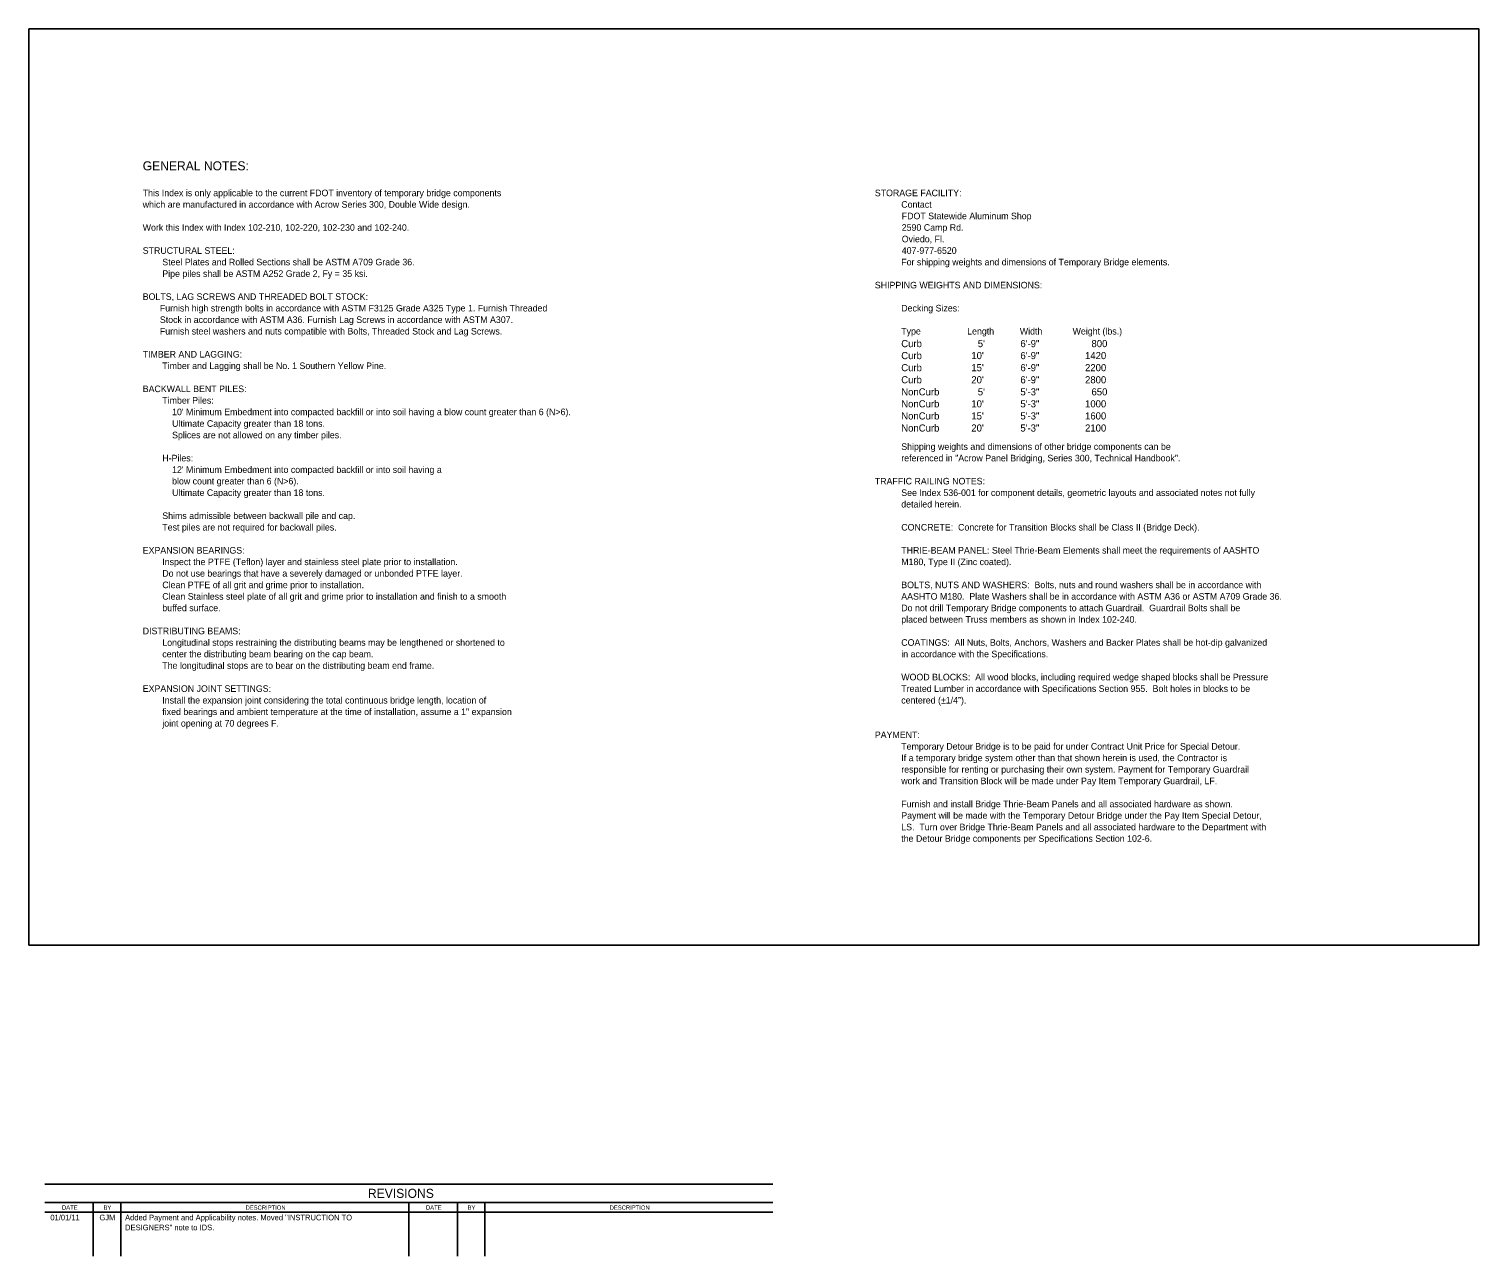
# Model space of a CAD drawing. Extents: x 0 to 2.25, y -0.21 to 0.88.
# Drawn here: x 0.001 to 1.283, y -0.211 to 0.875 of the extents above; entities that cross this region are included whole.
import ezdxf

# ---------------------------------------------------------------- set-up
doc = ezdxf.new("R2010")
doc.units = 0
for name, color, linetype in [('ActivePts-ConstElements', 7, 'Continuous'), ('Border', 7, 'Continuous'), ('TextStructures', 7, 'Continuous')]:
    doc.layers.add(name, color=color, linetype=linetype)

msp = doc.modelspace()

# ---------------------------------------------------------------- linework, layer by layer
at = {"layer": 'ActivePts-ConstElements'}
msp.add_lwpolyline([(0.0005, 0.0642), (1.2833, 0.0642), (1.2833, 0.875), (0.0005, 0.875)], close=True, dxfattribs=at)
at = {"layer": 'Border'}
for p, q in [((0.6585, -0.1475), (0.0144, -0.1475)), ((0.6585, -0.1636), (0.0144, -0.1636)), ((0.0574, -0.1636), (0.0574, -0.211)), ((0.0816, -0.1636), (0.0816, -0.211)), ((0.3365, -0.1636), (0.3365, -0.211)), ((0.3795, -0.1636), (0.3795, -0.211)), ((0.4037, -0.1636), (0.4037, -0.211)), ((0.0144, -0.1722), (0.6585, -0.1722))]:
    msp.add_line(p, q, dxfattribs=at)

# ---------------------------------------------------------------- texts
at = {"layer": 'TextStructures'}
for s, height, p in [('GENERAL NOTES:', 0.008, (0.1011, 0.7499)), ('This Index is only applicable to the current FDOT inventory of temporary bridge components', 0.005831, (0.1011, 0.727)), ('STORAGE FACILITY:', 0.005831, (0.7488, 0.727)), ('which are manufactured in accordance with Acrow Series 300, Double Wide design.', 0.005831, (0.1011, 0.7168)), ('Contact ', 0.00583, (0.7722, 0.7168)), ('           FDOT Statewide Aluminum Shop', 0.005831, (0.7488, 0.7066)), ('Work this Index with Index 102-210, 102-220, 102-230 and 102-240.', 0.005831, (0.1011, 0.6964)), ('           2590 Camp Rd.', 0.005831, (0.7488, 0.6964)), ('STRUCTURAL STEEL:', 0.005831, (0.1011, 0.676)), ('           407-977-6520', 0.005831, (0.7488, 0.676)), ('           Oviedo, Fl.', 0.005831, (0.7488, 0.6862)), ('        Steel Plates and Rolled Sections shall be ASTM A709 Grade 36. ', 0.005831, (0.1011, 0.6658)), ('For shipping weights and dimensions of Temporary Bridge elements.', 0.005831, (0.7722, 0.6658)), ('        Pipe piles shall be ASTM A252 Grade 2, Fy = 35 ksi.', 0.005831, (0.1011, 0.6556)), ('SHIPPING WEIGHTS AND DIMENSIONS:', 0.005831, (0.7488, 0.6454)), ('BOLTS, LAG SCREWS AND THREADED BOLT STOCK:', 0.005831, (0.1011, 0.6352)), ('       Furnish high strength bolts in accordance with ASTM F3125 Grade A325 Type 1. Furnish Threaded ', 0.005831, (0.1011, 0.625)), ('Decking Sizes:', 0.005831, (0.7722, 0.625)), ('       Stock in accordance with ASTM A36. Furnish Lag Screws in accordance with ASTM A307. ', 0.005831, (0.1011, 0.6148)), ('       Furnish steel washers and nuts compatible with Bolts, Threaded Stock and Lag Screws.', 0.005831, (0.1011, 0.6046)), ('Type', 0.00583, (0.7722, 0.6046)), ('Length', 0.00583, (0.8305, 0.6046)), ('Width', 0.00583, (0.8771, 0.6046)), ('Weight (lbs.)', 0.005831, (0.9238, 0.6046)), ('Curb', 0.0063, (0.7722, 0.5934)), ("5'", 0.0063, (0.8399, 0.5934)), ('6\'-9"', 0.0063, (0.8776, 0.5934)), ('800', 0.0063, (0.9405, 0.5934)), ('TIMBER AND LAGGING:', 0.005831, (0.1011, 0.5842)), ('        Timber and Lagging shall be No. 1 Southern Yellow Pine.', 0.005831, (0.1011, 0.574)), ('Curb', 0.0063, (0.7722, 0.5828)), ('Curb', 0.0063, (0.7722, 0.5721)), ("10'", 0.0063, (0.8342, 0.5828)), ("15'", 0.0063, (0.8342, 0.5721)), ('6\'-9"', 0.0063, (0.8776, 0.5828)), ('6\'-9"', 0.0063, (0.8776, 0.5721)), ('2200', 0.0063, (0.9348, 0.5721)), ('1420', 0.0063, (0.9348, 0.5828)), ('Curb', 0.0063, (0.7722, 0.5614)), ("20'", 0.0063, (0.8342, 0.5614)), ('6\'-9"', 0.0063, (0.8776, 0.5614)), ('2800', 0.0063, (0.9348, 0.5614)), ('BACKWALL BENT PILES:', 0.005831, (0.1011, 0.5536)), ('NonCurb', 0.0063, (0.7722, 0.5507)), ("5'", 0.0063, (0.8399, 0.5507)), ('5\'-3"', 0.0063, (0.8776, 0.5507)), ('650', 0.0063, (0.9405, 0.5507)), ('        Timber Piles: ', 0.005831, (0.1011, 0.5434)), ("            10' Minimum Embedment into compacted backfill or into soil having a blow count greater than 6 (N>6).", 0.005831, (0.1011, 0.5332)), ('NonCurb', 0.0063, (0.7722, 0.5401)), ("10'", 0.0063, (0.8342, 0.5401)), ('5\'-3"', 0.0063, (0.8776, 0.5401)), ('1000', 0.0063, (0.9348, 0.5401)), ('            Ultimate Capacity greater than 18 tons.', 0.005831, (0.1011, 0.5229)), ('NonCurb', 0.0063, (0.7722, 0.5294)), ("15'", 0.0063, (0.8342, 0.5294)), ('5\'-3"', 0.0063, (0.8776, 0.5294)), ('1600', 0.0063, (0.9348, 0.5294)), ('            Splices are not allowed on any timber piles.', 0.005831, (0.1011, 0.5127)), ('NonCurb', 0.0063, (0.7722, 0.5187)), ("20'", 0.0063, (0.8342, 0.5187)), ('5\'-3"', 0.0063, (0.8776, 0.5187)), ('2100', 0.0063, (0.9348, 0.5187)), ('Shipping weights and dimensions of other bridge components can be ', 0.005831, (0.7722, 0.5025)), ('        H-Piles: ', 0.005831, (0.1011, 0.4923)), ("            12' Minimum Embedment into compacted backfill or into soil having a ", 0.005831, (0.1011, 0.4821)), ('referenced in "Acrow Panel Bridging, Series 300, Technical Handbook".     ', 0.005831, (0.7722, 0.4923)), ('            blow count greater than 6 (N>6).', 0.005831, (0.1011, 0.4719)), ('TRAFFIC RAILING NOTES:', 0.005831, (0.7488, 0.4719)), ('            Ultimate Capacity greater than 18 tons.', 0.005831, (0.1011, 0.4617)), ('See Index 536-001 for component details, geometric layouts and associated notes not fully ', 0.005831, (0.7722, 0.4617)), ('detailed herein.', 0.005831, (0.7722, 0.4515)), ('        Test piles are not required for backwall piles.', 0.005831, (0.1011, 0.4311)), ('        Shims admissible between backwall pile and cap.', 0.005831, (0.1011, 0.4413)), ('CONCRETE:  Concrete for Transition Blocks shall be Class II (Bridge Deck).', 0.005831, (0.7722, 0.4311)), ('EXPANSION BEARINGS:', 0.005831, (0.1011, 0.4107)), ('THRIE-BEAM PANEL: Steel Thrie-Beam Elements shall meet the requirements of AASHTO ', 0.005831, (0.7722, 0.4107)), ('        Inspect the PTFE (Teflon) layer and stainless steel plate prior to installation.', 0.005831, (0.1011, 0.4005)), ('M180, Type II (Zinc coated).', 0.005831, (0.7722, 0.4005)), ('        Clean PTFE of all grit and grime prior to installation.', 0.005831, (0.1011, 0.3801)), ('        Do not use bearings that have a severely damaged or unbonded PTFE layer.', 0.005831, (0.1011, 0.3903)), ('BOLTS, NUTS AND WASHERS:  Bolts, nuts and round washers shall be in accordance with ', 0.005831, (0.7722, 0.3801)), ('        Clean Stainless steel plate of all grit and grime prior to installation and finish to a smooth ', 0.005831, (0.1011, 0.3699)), ('AASHTO M180.  Plate Washers shall be in accordance with ASTM A36 or ASTM A709 Grade 36.  ', 0.005831, (0.7722, 0.3699)), ('        buffed surface.', 0.005831, (0.1011, 0.3597)), ('Do not drill Temporary Bridge components to attach Guardrail.  Guardrail Bolts shall be ', 0.005831, (0.7722, 0.3597)), ('placed between Truss members as shown in Index 102-240.', 0.005831, (0.7722, 0.3495)), ('DISTRIBUTING BEAMS:', 0.005831, (0.1011, 0.3393)), ('        Longitudinal stops restraining the distributing beams may be lengthened or shortened to ', 0.005831, (0.1011, 0.3291)), ('COATINGS:  All Nuts, Bolts, Anchors, Washers and Backer Plates shall be hot-dip galvanized ', 0.005831, (0.7722, 0.3291)), ('        center the distributing beam bearing on the cap beam.', 0.005831, (0.1011, 0.3189)), ('in accordance with the Specifications.', 0.005831, (0.7722, 0.3189)), ('        The longitudinal stops are to bear on the distributing beam end frame.', 0.005831, (0.1011, 0.3087)), ('WOOD BLOCKS:  All wood blocks, including required wedge shaped blocks shall be Pressure ', 0.005831, (0.7722, 0.2985)), ('EXPANSION JOINT SETTINGS:', 0.005831, (0.1011, 0.2883)), ('        Install the expansion joint considering the total continuous bridge length, location of ', 0.005831, (0.1011, 0.278)), ('Treated Lumber in accordance with Specifications Section 955.  Bolt holes in blocks to be ', 0.005831, (0.7722, 0.2883)), ('centered (±1/4”).', 0.005831, (0.7722, 0.278)), ('        fixed bearings and ambient temperature at the time of installation, assume a 1" expansion ', 0.005831, (0.1011, 0.2678)), ('        joint opening at 70 degrees F. ', 0.005831, (0.1011, 0.2576)), ('PAYMENT:', 0.00583, (0.7488, 0.2474)), ('Temporary Detour Bridge is to be paid for under Contract Unit Price for Special Detour.', 0.005831, (0.7722, 0.2372)), ('If a temporary bridge system other than that shown herein is used, the Contractor is ', 0.005831, (0.7722, 0.227)), ('responsible for renting or purchasing their own system. Payment for Temporary Guardrail ', 0.005831, (0.7722, 0.2168)), ('work and Transition Block will be made under Pay Item Temporary Guardrail, LF.', 0.005831, (0.7722, 0.2066)), ('Furnish and install Bridge Thrie-Beam Panels and all associated hardware as shown.  ', 0.005831, (0.7722, 0.1862)), ('Payment will be made with the Temporary Detour Bridge under the Pay Item Special Detour, ', 0.005831, (0.7722, 0.176)), ('LS.  Turn over Bridge Thrie-Beam Panels and all associated hardware to the Department with ', 0.005831, (0.7722, 0.1658)), ('the Detour Bridge components per Specifications Section 102-6.', 0.005831, (0.7722, 0.1556)), ('REVISIONS', 0.00802, (0.3003, -0.1595)), ('BY', 0.00375, (0.0664, -0.17)), ('BY', 0.00375, (0.3885, -0.17)), ('01/01/11', 0.005, (0.0194, -0.1794)), ('GJM', 0.005, (0.0628, -0.1794)), ('Added Payment and Applicability notes. Moved "INSTRUCTION TO', 0.005, (0.0855, -0.1794)), ('DESIGNERS" note to IDS.', 0.005, (0.0855, -0.1882))]:
    msp.add_text(s, height=height, dxfattribs=at).set_placement(p)
for s, height, rotation, p in [('DATE', 0.00374, 359.8693, (0.0297, -0.1699)), ('DESCRIPTION', 0.003752, 0.0498, (0.1921, -0.17)), ('DATE', 0.00374, 359.8693, (0.3517, -0.1699)), ('DESCRIPTION', 0.003752, 0.0498, (0.5142, -0.17))]:
    msp.add_text(s, height=height, rotation=rotation, dxfattribs=at).set_placement(p)

doc.saveas('drawing.dxf')
